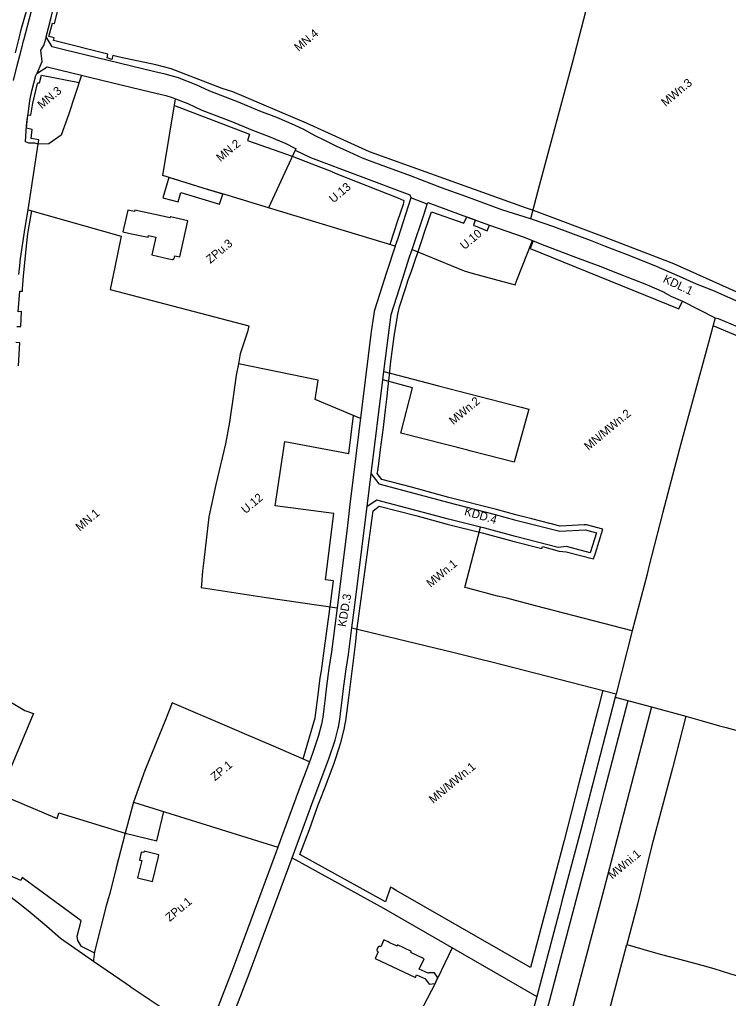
# Model space of a CAD drawing. Extents: x 7418616 to 7420822, y 5550745 to 5553106.
# Drawn here: x 7420041 to 7420462, y 5551038 to 5551619 of the extents above; entities that cross this region are included whole.
import ezdxf

# ---------------------------------------------------------------- set-up
doc = ezdxf.new("R2010")
doc.units = 0
for name, color, linetype in [('granica obszaru objętego planem', 7, 'Continuous'), ('linie rozgraniczające', 7, 'Continuous'), ('nieprzekraczalne linie lokalizacyjne', 7, 'Continuous'), ('nieprzekraczalne linie zabudowy', 7, 'Continuous'), ('obowiązujące linie zabudowy', 7, 'Continuous'), ('przeznaczenia terenów', 7, 'Continuous')]:
    doc.layers.add(name, color=color, linetype=linetype)

msp = doc.modelspace()

# ---------------------------------------------------------------- linework, layer by layer
at = {"layer": 'granica obszaru objętego planem'}
msp.add_lwpolyline([(7420129.73, 5551029.01), (7420107.22, 5551044.12), (7420106.69, 5551044.49), (7420104.17, 5551046.18), (7420084.7, 5551059.47), (7420065.1, 5551073.14), (7420057.01, 5551080.26), (7420047.07, 5551088.52), (7420041.04, 5551093.52), (7420000.75, 5551124.25)], dxfattribs=at)
at = {"layer": 'linie rozgraniczające'}
for p, q in [((7420045.85, 5551506.07), (7420051.79, 5551545.12)), ((7420204.6, 5551541.6), (7420188.68, 5551507.37)), ((7420283.03, 5551509.41), (7420273.3, 5551513.17)), ((7420264.07, 5551484.61), (7420188.68, 5551507.37)), ((7420249.83, 5551349.36), (7420256.75, 5551405.03)), ((7420256.75, 5551405.03), (7420257.37, 5551410.03)), ((7420247.39, 5551329.76), (7420249.83, 5551349.36)), ((7420404.81, 5551255.96), (7420395.28, 5551218.62)), ((7420395.28, 5551218.62), (7420394.76, 5551216.63)), ((7420394.76, 5551216.63), (7420416.4, 5551210.73)), ((7420416.4, 5551210.73), (7420436.76, 5551205.18)), ((7420108.42, 5551154.21), (7420103.62, 5551135.67)), ((7420108.42, 5551154.21), (7420194.32, 5551127.45))]:
    msp.add_line(p, q, dxfattribs=at)
for points in [[(7420393.2, 5551686.36), (7420379.89, 5551634.75), (7420369.22, 5551593.33), (7420349.6, 5551520.43), (7420344.48, 5551500.75)], [(7420056.52, 5551608.96), (7420059.58, 5551620.5), (7420064.57, 5551641.06), (7420065.09, 5551643.07), (7420064.82, 5551643.14), (7420069.28, 5551660.28), (7420069.58, 5551660.29), (7420071.45, 5551667.47)], [(7420037.19, 5551583.05), (7420039.4, 5551591.99), (7420041.71, 5551600.73), (7420041.78, 5551601.13), (7420041.87, 5551601.52), (7420041.98, 5551601.9), (7420042.12, 5551602.25), (7420043.24, 5551606.48), (7420043.61, 5551607.69), (7420047.77, 5551623.56), (7420050.61, 5551635.2), (7420052.75, 5551644.09), (7420055.5, 5551654.67)], [(7420056.52, 5551608.96), (7420055.25, 5551604.17), (7420053.33, 5551600.95), (7420054.12, 5551594.17), (7420050.99, 5551587.11)], [(7420344.48, 5551500.75), (7420327.51, 5551506.14), (7420306.03, 5551513.98), (7420291.54, 5551519.2), (7420273.05, 5551526.35), (7420258.4, 5551531.63), (7420248.72, 5551535.26), (7420244.56, 5551536.85), (7420236.87, 5551540.31), (7420229.36, 5551543.85), (7420222.16, 5551547.28), (7420216.57, 5551550.15), (7420209.77, 5551553.86), (7420204.17, 5551556.53), (7420193.64, 5551561.01), (7420183.68, 5551564.85), (7420170.99, 5551570.19), (7420160.65, 5551573.99), (7420153.91, 5551576.7), (7420145.69, 5551580.45), (7420135.63, 5551584.34), (7420135.2, 5551584.49), (7420130.92, 5551585.78), (7420127.34, 5551586.72), (7420121.17, 5551588.07), (7420086.15, 5551596.65), (7420068.14, 5551601.11), (7420060.1, 5551602.94), (7420056.52, 5551608.96)], [(7420050.99, 5551587.11), (7420057.13, 5551591.1), (7420065.38, 5551589.22), (7420077.64, 5551586.19)], [(7420051.79, 5551545.12), (7420049.9, 5551545.66), (7420046.22, 5551545.7), (7420044.43, 5551546.59), (7420044.74, 5551553.09), (7420045.14, 5551558.17), (7420046.06, 5551564.5), (7420046.98, 5551571.11), (7420048.19, 5551576.77), (7420050.48, 5551585.96), (7420050.99, 5551587.11)], [(7420077.64, 5551586.19), (7420069.82, 5551562.67), (7420065.58, 5551550.44), (7420058.26, 5551545.42), (7420051.79, 5551545.12)], [(7420077.64, 5551586.19), (7420083.23, 5551584.8), (7420118.5, 5551576.16), (7420124.36, 5551574.89), (7420127.69, 5551574.01), (7420131.45, 5551572.88), (7420133.55, 5551572.07)], [(7420188.68, 5551507.37), (7420164.8, 5551514.7), (7420149.86, 5551518.98), (7420126, 5551526.51), (7420133.55, 5551572.07)], [(7420133.55, 5551572.07), (7420140.79, 5551569.27), (7420149.17, 5551565.45), (7420156.36, 5551562.57), (7420166.38, 5551558.89), (7420179.2, 5551553.49), (7420189.15, 5551549.66), (7420199.05, 5551545.46), (7420204.09, 5551543.06), (7420204.93, 5551542.6), (7420204.6, 5551541.6)], [(7420204.6, 5551541.6), (7420213.63, 5551537.27), (7420272.83, 5551515.06), (7420273.43, 5551513.56), (7420273.3, 5551513.17)], [(7420273.3, 5551513.17), (7420265.51, 5551489.05), (7420264.07, 5551484.77), (7420264.07, 5551484.61)], [(7420274.06, 5551482.59), (7420281.39, 5551504.39), (7420283.03, 5551509.41)], [(7420283.03, 5551509.41), (7420283.36, 5551510.41), (7420308.01, 5551501.43), (7420320, 5551497.12), (7420340.69, 5551489.89), (7420345.69, 5551487.87)], [(7420040.36, 5551467.76), (7420040.89, 5551472.88), (7420041.44, 5551477.21), (7420044.19, 5551495.63), (7420045.85, 5551506.07)], [(7420045.85, 5551506.07), (7420101.19, 5551490.53), (7420097.36, 5551472.07), (7420094.59, 5551458.73), (7420177.15, 5551437.19)], [(7420470.48, 5551450.29), (7420466.61, 5551451.98), (7420452.83, 5551458.21), (7420443.04, 5551462.02), (7420433.08, 5551466.52), (7420417.91, 5551473.01), (7420401.57, 5551479.53), (7420389.11, 5551484.32), (7420380.2, 5551487.87), (7420358.35, 5551496), (7420345.61, 5551500.39), (7420344.48, 5551500.75)], [(7420274.06, 5551482.59), (7420304.97, 5551469.8), (7420310.36, 5551468.34), (7420335.24, 5551461.57), (7420336.39, 5551464.44), (7420345.69, 5551487.87)], [(7420345.69, 5551487.87), (7420351.43, 5551485.55), (7420365.49, 5551480.18), (7420369.51, 5551478.65), (7420379.79, 5551474.88), (7420384.63, 5551472.97), (7420397.09, 5551468.18), (7420413.32, 5551461.71), (7420423.93, 5551457.17), (7420425.12, 5551456.47), (7420427.77, 5551454.91), (7420434.73, 5551451.92), (7420454.26, 5551442)], [(7420264.07, 5551484.61), (7420258.94, 5551468.87), (7420251.73, 5551446.53), (7420251.65, 5551446.28), (7420251.52, 5551445.63), (7420251.18, 5551442.9), (7420249.69, 5551433.89), (7420237.11, 5551330.96), (7420235.48, 5551316.7), (7420229.63, 5551269.67)], [(7420257.37, 5551410.03), (7420261.58, 5551443.85), (7420268.39, 5551464.95), (7420272.63, 5551478.14), (7420274.06, 5551482.59)], [(7420454.26, 5551442), (7420450.05, 5551426.5), (7420433.77, 5551367.03), (7420433.01, 5551364.21), (7420423.12, 5551326.4), (7420414.49, 5551293.41), (7420413.79, 5551289.72), (7420404.81, 5551255.96)], [(7420454.26, 5551442), (7420456.01, 5551441.5), (7420474.85, 5551433.74), (7420485.44, 5551429.34), (7420494.4, 5551425.53), (7420504.04, 5551421.55), (7420514.44, 5551417.1), (7420518.17, 5551415.56), (7420524.61, 5551412.91), (7420531.08, 5551410.21), (7420558.49, 5551398.24), (7420565.01, 5551395.49)], [(7420177.15, 5551437.19), (7420176.24, 5551433.63), (7420173.89, 5551426.42), (7420171.94, 5551420.59), (7420170.83, 5551414.66), (7420169.51, 5551407.84), (7420167.92, 5551396.39), (7420165.49, 5551380.03), (7420163.26, 5551367.05), (7420157.37, 5551342.98), (7420153.37, 5551323.78), (7420150.23, 5551297.76), (7420149.5, 5551291.33), (7420148.86, 5551283.57), (7420148.75, 5551281.63), (7420187.44, 5551275.84), (7420229.63, 5551269.67)], [(7420243.37, 5551382.23), (7420216.46, 5551393.53), (7420218.24, 5551405), (7420170.83, 5551414.66)], [(7420257.37, 5551410.03), (7420283.02, 5551403.34), (7420289.77, 5551401.58), (7420326.62, 5551391.98), (7420332.75, 5551390.38), (7420338.83, 5551388.8), (7420343.39, 5551387.61), (7420334.8, 5551356.21), (7420309.24, 5551362.77), (7420307.3, 5551363.27), (7420267.47, 5551373.5), (7420274.42, 5551400.42), (7420256.75, 5551405.03)], [(7420249.83, 5551349.36), (7420254.24, 5551343.25), (7420273.01, 5551338.36), (7420295.12, 5551332.37), (7420323.51, 5551325.17), (7420335.02, 5551321.95), (7420344.52, 5551319.58), (7420361.87, 5551315.15), (7420377.21, 5551315.98), (7420383.68, 5551314.3), (7420379.95, 5551302.41), (7420379.93, 5551302.36), (7420365.86, 5551306.02), (7420360.95, 5551305.58), (7420335.6, 5551312.04), (7420317.34, 5551316.99), (7420314.67, 5551317.64)], [(7420238.23, 5551257.8), (7420239.74, 5551268.26), (7420247.39, 5551329.76)], [(7420314.67, 5551317.64), (7420295.69, 5551322.23), (7420277.04, 5551327.36), (7420253.04, 5551333.54), (7420247.39, 5551329.76)], [(7420404.81, 5551255.96), (7420347.5, 5551270.87), (7420330.42, 5551275.31), (7420324.77, 5551276.63), (7420307.13, 5551281.26), (7420305.42, 5551281.69), (7420314.67, 5551317.64)], [(7420229.63, 5551269.67), (7420228.1, 5551258.99), (7420226.09, 5551243.46), (7420224.59, 5551233.56), (7420223.17, 5551223.01), (7420222.36, 5551215.92), (7420221.56, 5551209.72), (7420220.96, 5551204.73), (7420220.31, 5551200.57), (7420218.51, 5551193.84), (7420214.97, 5551183.12), (7420213.12, 5551178.23)], [(7420202.83, 5551121), (7420215.92, 5551156.82), (7420224.63, 5551179.82), (7420228.33, 5551191.05), (7420230.24, 5551198.2), (7420230.35, 5551198.73), (7420231.06, 5551203.26), (7420231.68, 5551208.44), (7420232.49, 5551214.72), (7420233.29, 5551221.71), (7420234.44, 5551230.17), (7420234.67, 5551232.07), (7420236.19, 5551241.98), (7420238.23, 5551257.8)], [(7420238.23, 5551257.8), (7420298.23, 5551243.24), (7420314.94, 5551239.23), (7420320.68, 5551237.73), (7420395.28, 5551218.62)], [(7419994.65, 5551238.46), (7420001.56, 5551236.47), (7420018.02, 5551224.98), (7420028.47, 5551217.79), (7420043.94, 5551208.61), (7420049.1, 5551206.8), (7420047.93, 5551204.04), (7420037.16, 5551178.61), (7420028.79, 5551158.84), (7420063.17, 5551144.43), (7420064.18, 5551147.79), (7420103.62, 5551135.67)], [(7420213.12, 5551178.23), (7420191.68, 5551187.36), (7420174.4, 5551194.73), (7420168.52, 5551197.27), (7420131.43, 5551213.27), (7420127.46, 5551203.14), (7420115.19, 5551173.08), (7420108.42, 5551154.21)], [(7420394.76, 5551216.63), (7420382.82, 5551170.58), (7420374.29, 5551137.67), (7420363.31, 5551096.1), (7420362.04, 5551091.26), (7420348.19, 5551038.78)], [(7420416.4, 5551210.73), (7420391.25, 5551114.44), (7420387.03, 5551098.6), (7420375.73, 5551055.84), (7420365.88, 5551018.47), (7420386.78, 5551013.02), (7420393.53, 5551038.97), (7420401.62, 5551069.56)], [(7420436.76, 5551205.18), (7420428.86, 5551174.38), (7420416.57, 5551128.39), (7420407.97, 5551093.6), (7420401.62, 5551069.56)], [(7420436.76, 5551205.18), (7420446.47, 5551202.49), (7420456.79, 5551199.59), (7420460.64, 5551198.52), (7420467.79, 5551196.53), (7420478.23, 5551193.62), (7420488.45, 5551190.91), (7420498.58, 5551188.31), (7420519.65, 5551182.3)], [(7420213.12, 5551178.23), (7420206.37, 5551160.4), (7420194.32, 5551127.45)], [(7420103.62, 5551135.67), (7420098.31, 5551115.22), (7420094.37, 5551099.93), (7420093.43, 5551096.67), (7420092.29, 5551092.5), (7420085.31, 5551065.27), (7420085.06, 5551063.63), (7420084.76, 5551060.55), (7420084.7, 5551059.47)], [(7420194.32, 5551127.45), (7420193.34, 5551124.74), (7420167.72, 5551055.81), (7420151.93, 5551014.95)], [(7420129.73, 5551029.01), (7420107.22, 5551044.12), (7420106.69, 5551044.49), (7420104.17, 5551046.18), (7420084.7, 5551059.47), (7420065.1, 5551073.14), (7420057.01, 5551080.26), (7420047.07, 5551088.52), (7420041.04, 5551093.52), (7420000.75, 5551124.25)], [(7420160.8, 5551009.6), (7420177.25, 5551052.17), (7420202.83, 5551121)], [(7420202.83, 5551121), (7420257.06, 5551091.11), (7420348.19, 5551038.78)], [(7420401.62, 5551069.56), (7420411.19, 5551066.74), (7420421.57, 5551063.94), (7420432.94, 5551060.93), (7420442.75, 5551058.24), (7420453.49, 5551055.26), (7420463.38, 5551052.22), (7420483.93, 5551046.39), (7420448.44, 5550910.56), (7420443.54, 5550891.79)], [(7420348.19, 5551038.78), (7420327.59, 5550962.8), (7420324.67, 5550951.81), (7420318.94, 5550930.36), (7420316.17, 5550919.88)]]:
    msp.add_lwpolyline(points, dxfattribs=at)
at = {"layer": 'nieprzekraczalne linie lokalizacyjne'}
msp.add_lwpolyline([(7420297.83, 5551067.7), (7420295.49, 5551062.73), (7420289.38, 5551049.77), (7420289.25, 5551049.5), (7420288.98, 5551048.92), (7420288.08, 5551047.01), (7420287.98, 5551046.8), (7420287.83, 5551046.48), (7420260.94, 5550994.94), (7420254.02, 5550982.09), (7420250.32, 5550975.22), (7420297.33, 5550948), (7420305.3, 5550943.4), (7420314.47, 5550938.1), (7420320.13, 5550934.82)], dxfattribs=at)
at = {"layer": 'nieprzekraczalne linie zabudowy'}
for points in [[(7420058.23, 5551609.09), (7420060.34, 5551617.14), (7420061.53, 5551616.82), (7420066.89, 5551638.06)], [(7420038.39, 5551599.48), (7420040.84, 5551608.88), (7420041.85, 5551613.31), (7420045.25, 5551625.61)], [(7420472.51, 5551454.93), (7420429.6, 5551473.97), (7420388.35, 5551489.86), (7420346.33, 5551505.75), (7420342.04, 5551507.19), (7420248.7, 5551540.53), (7420211.34, 5551557.63), (7420167.56, 5551576.32), (7420161.25, 5551578.19), (7420130.92, 5551589.95), (7420121.8, 5551592.35), (7420100.28, 5551596.78), (7420096.27, 5551597.79), (7420095.68, 5551595.55), (7420092.8, 5551596.42), (7420093.36, 5551598.64), (7420060.97, 5551606.77), (7420061.32, 5551608.28), (7420058.23, 5551609.09)], [(7420051.79, 5551545.12), (7420052.32, 5551547.8), (7420047.71, 5551548.51), (7420048.32, 5551553.94), (7420044.87, 5551554.66), (7420045.78, 5551562.57), (7420047.44, 5551562.29), (7420048.73, 5551569.51), (7420051.49, 5551581.15), (7420051.6, 5551581.68), (7420052.74, 5551581.52), (7420053.9, 5551586.24), (7420076.15, 5551581.73)], [(7420132.91, 5551568.23), (7420177.37, 5551551.19), (7420176.17, 5551547.35), (7420202.83, 5551538.08), (7420214.54, 5551533.39), (7420226.32, 5551528.82), (7420226.61, 5551528.68), (7420229.27, 5551527.53), (7420265.52, 5551513.26), (7420269.26, 5551511.61), (7420268.73, 5551509.26), (7420265.43, 5551499.58), (7420263.19, 5551492.85), (7420260.84, 5551485.58)], [(7420039.2, 5551436.8), (7420041.55, 5551436.77), (7420041.95, 5551445.68), (7420039.91, 5551445.49), (7420041.03, 5551457.85), (7420042.54, 5551457.87), (7420042.6, 5551459.13), (7420042.96, 5551464.38), (7420043.1, 5551466.95), (7420045.04, 5551486.51), (7420045.75, 5551491.91), (7420046.79, 5551497.86), (7420048.06, 5551505.45)], [(7420387.37, 5551220.64), (7420384.75, 5551209.89), (7420373.23, 5551165.48), (7420364.38, 5551131.46), (7420344.44, 5551055.92), (7420264.6, 5551101.77), (7420262.43, 5551103), (7420261.2, 5551103.67), (7420258.33, 5551094.97), (7420207.37, 5551123.06), (7420213.17, 5551137.93), (7420218.33, 5551152.64), (7420220.18, 5551157.5), (7420222.98, 5551164.7), (7420225.58, 5551171.67), (7420227.5, 5551176.75), (7420228.82, 5551180.35), (7420231.81, 5551189.65), (7420233.7, 5551197.35), (7420234.37, 5551200.77), (7420234.65, 5551202.55), (7420236.39, 5551216.07), (7420238.05, 5551228.81), (7420240.4, 5551247.88), (7420241.52, 5551257.53), (7420250.97, 5551327.37), (7420254.55, 5551330.05), (7420276.27, 5551324.46), (7420294.9, 5551319.34), (7420316.6, 5551314.09), (7420334.82, 5551309.14), (7420351.19, 5551304.97), (7420351.55, 5551306.08), (7420361.46, 5551303.32), (7420365.61, 5551302.97), (7420381.92, 5551298.75), (7420382.98, 5551302.06), (7420387.49, 5551316.42), (7420377.77, 5551318.93), (7420377.6, 5551318.97), (7420377.21, 5551319.02), (7420376.82, 5551319.02), (7420376.62, 5551319), (7420376.25, 5551318.93), (7420362.17, 5551318.17), (7420345.26, 5551322.49), (7420335.79, 5551324.85), (7420324.28, 5551328.07), (7420295.88, 5551335.27), (7420273.76, 5551341.26), (7420256.04, 5551345.88), (7420253.4, 5551349.54), (7420253.64, 5551351.01), (7420254.44, 5551357.04), (7420255.37, 5551363.69), (7420257.13, 5551376.84), (7420258.36, 5551387.34), (7420259.19, 5551395.17), (7420259.62, 5551399.59), (7420260.39, 5551406.34), (7420261.46, 5551415.98), (7420263.33, 5551430.8), (7420265.57, 5551444.19), (7420266.56, 5551448.53), (7420270.27, 5551459.89), (7420271.83, 5551464.45), (7420273.76, 5551469.72), (7420279.73, 5551487.36), (7420281.64, 5551493.43), (7420285.65, 5551505), (7420304.91, 5551498.31), (7420306.58, 5551501.95), (7420311.65, 5551500.12), (7420310.62, 5551496.91), (7420311.47, 5551496.6), (7420318.74, 5551493.72), (7420320, 5551497.12), (7420340.69, 5551489.89), (7420346.05, 5551487.72), (7420344.18, 5551483.09), (7420432.57, 5551447.34), (7420434.86, 5551451.85), (7420454.26, 5551442)], [(7420723.51, 5550986.46), (7420752.47, 5551095.47), (7420746.43, 5551097.17), (7420760.21, 5551147.18), (7420780.65, 5551223.67), (7420795.62, 5551280.83), (7420770.13, 5551300.65), (7420689.35, 5551335.99), (7420592.51, 5551377.97), (7420586.54, 5551374.47), (7420554.55, 5551252.27), (7420535.12, 5551178.2), (7420534.04, 5551174.16), (7420514.73, 5551179.31), (7420530.25, 5551238.1), (7420562.35, 5551361.15), (7420568.88, 5551384.83), (7420562.96, 5551390.99), (7420452.94, 5551437.15)], [(7420040.13, 5551413.47), (7420040.96, 5551427.09), (7420038.51, 5551427.3)], [(7420209.39, 5551179.82), (7420216.43, 5551204.27), (7420218.32, 5551218), (7420219.52, 5551228.03), (7420220.16, 5551232.25), (7420222.45, 5551248.57), (7420224.42, 5551263.01), (7420225.18, 5551268.91), (7420225.22, 5551269.19), (7420225.42, 5551270.21), (7420227.3, 5551285.67), (7420222.68, 5551286.28), (7420227.53, 5551325.79), (7420192.78, 5551330.26), (7420198.46, 5551368.56), (7420236.5, 5551361.4), (7420239.25, 5551383.96)], [(7420324.13, 5550949.79), (7420331.82, 5550947.8), (7420355.92, 5551036.71), (7420379.85, 5551127.4), (7420388.72, 5551161.46), (7420402.49, 5551214.53)], [(7420103.62, 5551135.67), (7420122.41, 5551131.11), (7420126.63, 5551148.54)], [(7420085.21, 5551064.62), (7420077.64, 5551068.32), (7420075.35, 5551071.93), (7420075, 5551074.55), (7420077.32, 5551083.6), (7420042.43, 5551109.43), (7420041.53, 5551107.62), (7420013.42, 5551119.86)]]:
    msp.add_lwpolyline(points, dxfattribs=at)
at = {"layer": 'obowiązujące linie zabudowy'}
for points in [[(7420129.43, 5551525.39), (7420125.98, 5551513.36), (7420134.97, 5551510.8), (7420136.65, 5551516.45), (7420159.72, 5551509.41), (7420161.58, 5551515.52), (7420149.86, 5551518.98), (7420140.32, 5551521.99), (7420129.43, 5551525.39)], [(7420105.12, 5551505.96), (7420103.98, 5551500.86), (7420102.22, 5551493), (7420107.36, 5551491.94), (7420117.19, 5551489.9), (7420117.43, 5551490.86), (7420121.72, 5551489.95), (7420119.48, 5551479.35), (7420129.44, 5551477.09), (7420131.64, 5551476.61), (7420132.66, 5551477.31), (7420132.99, 5551478.82), (7420136.1, 5551478.14), (7420140.74, 5551499.69), (7420130.49, 5551501.93), (7420130.36, 5551501.32), (7420109.33, 5551505.87), (7420109.15, 5551505.06), (7420105.12, 5551505.96)], [(7420123.65, 5551122.91), (7420121.15, 5551123.53), (7420120.48, 5551123.7), (7420114.8, 5551125.1), (7420114.57, 5551124.18), (7420113.17, 5551124.55), (7420112.01, 5551119.79), (7420113.43, 5551119.44), (7420110.96, 5551109.16), (7420119.83, 5551106.93), (7420123.15, 5551120.81), (7420123.65, 5551122.91)], [(7420261.28, 5551070.44), (7420260.51, 5551070.8), (7420259.93, 5551071.08), (7420257.33, 5551072.3), (7420255.41, 5551068.22), (7420254.74, 5551068.54), (7420253.86, 5551068.2), (7420253.04, 5551066.49), (7420253.37, 5551065.55), (7420254, 5551065.25), (7420252.13, 5551061.28), (7420276.03, 5551050.04), (7420276.78, 5551051.63), (7420282.06, 5551049.09), (7420281.99, 5551048.94), (7420284.22, 5551046.06), (7420287.83, 5551046.48), (7420287.98, 5551046.8), (7420289.25, 5551049.5), (7420289.38, 5551049.77), (7420287.38, 5551052.83), (7420283.77, 5551052.68), (7420283.68, 5551052.5), (7420278.37, 5551054.99), (7420281.23, 5551061.05), (7420273.42, 5551064.74), (7420273.74, 5551065.42), (7420265.47, 5551069.32), (7420265.14, 5551068.63), (7420264.49, 5551068.93), (7420263.08, 5551069.59), (7420261.28, 5551070.44)]]:
    msp.add_lwpolyline(points, dxfattribs=at)

# ---------------------------------------------------------------- texts
at = {"layer": 'przeznaczenia terenów'}
for s, rotation, p in [('MN.4', 39.84394, (7420206.61, 5551599.96)), ('MN.3', 39.84394, (7420053.99, 5551565.88)), ('MWn.3', 39.84394, (7420424.73, 5551567.25)), ('MN.2', 39.84394, (7420160.22, 5551534.4)), ('U.13', 39.84394, (7420227.29, 5551509.9)), ('U.10', 39.84394, (7420305.19, 5551482.16)), ('ZPu.3', 39.84394, (7420154.16, 5551473.96)), ('KDL.1', 334.52279, (7420422.77, 5551463.35)), ('MWn.2', 39.84394, (7420298.63, 5551378.1)), ('MN/MWn.2', 39.84394, (7420378.92, 5551362.9)), ('U.12', 39.84394, (7420175.08, 5551325.26)), ('KDD.4', 343.64423, (7420304.75, 5551324.92)), ('MN.1', 39.84394, (7420076.59, 5551314.9)), ('MWn.1', 39.84394, (7420285.14, 5551281.48)), ('KDD.3', 80.2307, (7420234.7, 5551258.07)), ('ZP.1', 39.84394, (7420156.93, 5551166.5)), ('MN/MWn.1', 39.84394, (7420286.66, 5551153.08)), ('MWni.1', 39.84394, (7420393.08, 5551108.13)), ('ZPu.1', 39.84394, (7420130.04, 5551082.92))]:
    msp.add_text(s, height=5, rotation=rotation, dxfattribs=at).set_placement(p)

doc.saveas('drawing.dxf')
